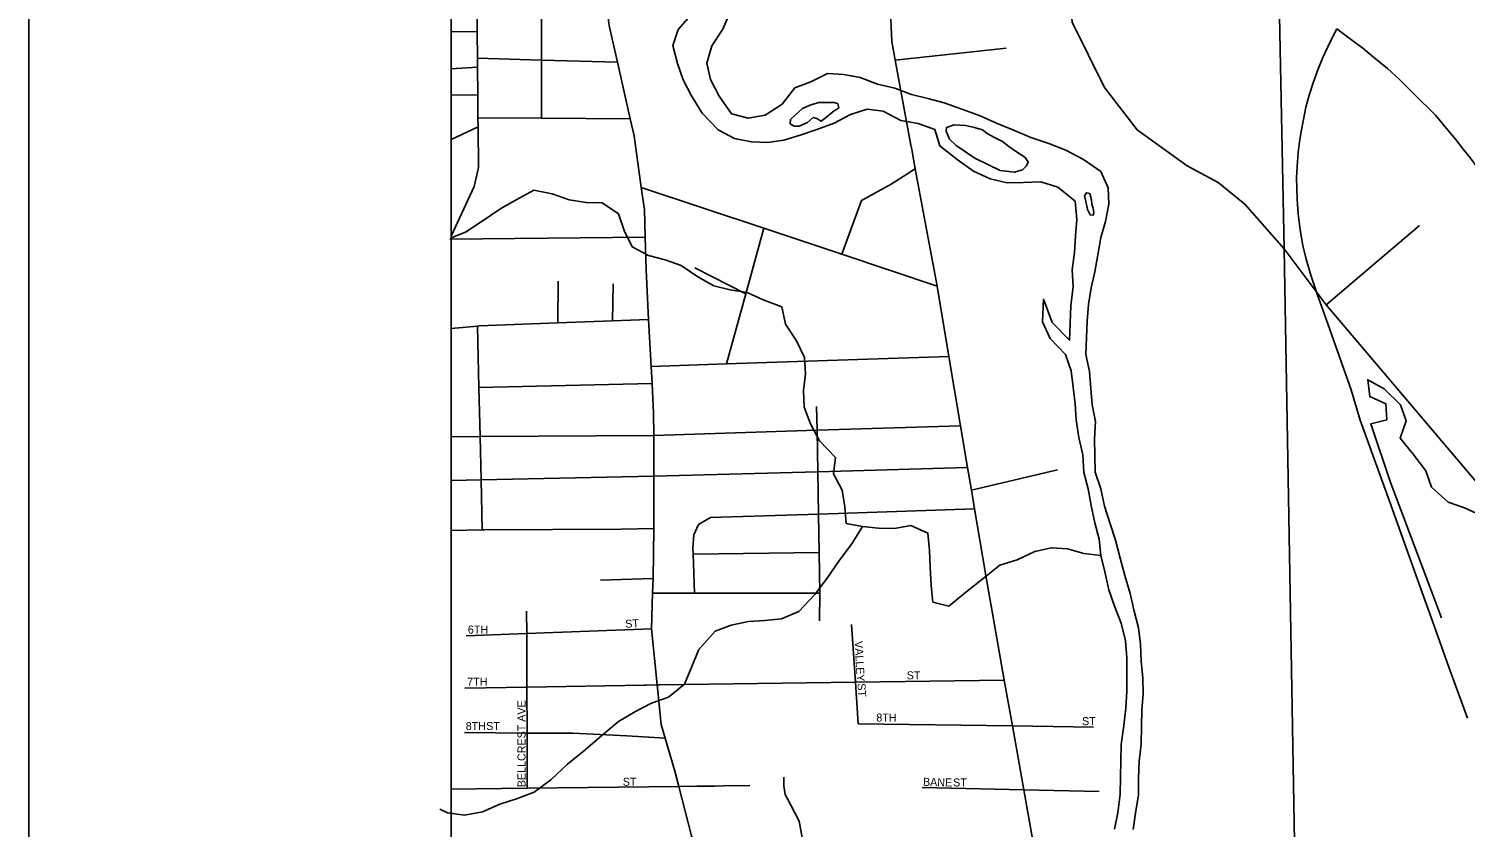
# Model space of a CAD drawing. Extents: x -37878.7 to -37844.7, y -19791.4 to -19769.4.
# Drawn here: x -37876.65 to -37874.951, y -19773.183 to -19772.239 of the extents above; entities that cross this region are included whole.
import ezdxf

# ---------------------------------------------------------------- set-up
doc = ezdxf.new("R2010")
doc.units = 0
for name, color, linetype in [('GM_X_City_Street', 7, 'Continuous'), ('GM_X_County_Road', 7, 'Continuous'), ('GM_X_Major_River', 7, 'Continuous'), ('GM_X_Minor_River', 7, 'Continuous'), ('GM_X_Rail_Line', 7, 'Continuous'), ('GM_X_State_Route', 7, 'Continuous'), ('GM_X_Township', 7, 'Continuous'), ('GM_X_Township_Subdivision', 7, 'Continuous'), ('GM_X_Township_Subdivision_Text', 7, 'Continuous'), ('SH_Border', 7, 'Continuous'), ('SH_Data', 7, 'Continuous')]:
    doc.layers.add(name, color=color, linetype=linetype)

msp = doc.modelspace()

# ---------------------------------------------------------------- linework, layer by layer
at = {"layer": 'GM_X_City_Street'}
for points in [[(-37875.146, -19772.5239), (-37875.1648, -19772.4986), (-37875.2116, -19772.4458), (-37875.243, -19772.4204), (-37875.2799, -19772.4006), (-37875.3389, -19772.3581), (-37875.3775, -19772.308), (-37875.416, -19772.2309), (-37875.4204, -19772.1824), (-37875.4323, -19771.9563)], [(-37875.9135, -19772.9483), (-37875.9122, -19772.9059), (-37875.9117, -19772.8885), (-37875.9108, -19772.8296), (-37875.9109, -19772.7676), (-37875.9109, -19772.7194), (-37875.911, -19772.6933), (-37875.9128, -19772.6581), (-37875.9139, -19772.6379), (-37875.9169, -19772.5822), (-37875.92, -19772.5236), (-37875.9209, -19772.4851), (-37875.9217, -19772.4523), (-37875.9256, -19772.4261), (-37875.9342, -19772.365), (-37875.9387, -19772.345), (-37875.9538, -19772.2781), (-37875.9632, -19772.2368), (-37875.9642, -19772.2318), (-37875.9748, -19772.1441), (-37875.9732, -19772.0332), (-37875.9723, -19771.9774)], [(-37876.0436, -19772.3444), (-37876.0436, -19772.2756), (-37876.0436, -19772.1572), (-37876.0436, -19772.0909), (-37876.0382, -19772.0362)], [(-37875.6056, -19772.3812), (-37875.6065, -19772.3761), (-37875.6251, -19772.2758), (-37875.6293, -19772.2535), (-37875.6314, -19772.201), (-37875.6347, -19772.121), (-37875.6353, -19772.1059)], [(-37876.1504, -19772.2416), (-37876.1197, -19772.2422)], [(-37876.1194, -19772.2734), (-37876.0436, -19772.2756), (-37875.9538, -19772.2781)], [(-37875.6251, -19772.2758), (-37875.494, -19772.2615)], [(-37876.1504, -19772.2861), (-37876.1194, -19772.284)], [(-37876.1504, -19772.3171), (-37876.1191, -19772.3166)], [(-37876.1189, -19772.344), (-37876.0436, -19772.3444), (-37875.9387, -19772.345)], [(-37876.1504, -19772.3694), (-37876.1188, -19772.3546)], [(-37875.5148, -19772.9033), (-37875.518, -19772.8852), (-37875.5312, -19772.8063), (-37875.535, -19772.7841), (-37875.5395, -19772.7575), (-37875.5478, -19772.7081), (-37875.5616, -19772.626), (-37875.5756, -19772.5429), (-37875.6014, -19772.404), (-37875.6056, -19772.3812)], [(-37875.6885, -19772.5052), (-37875.6652, -19772.4415), (-37875.6299, -19772.4223), (-37875.6014, -19772.404)], [(-37875.9256, -19772.4261), (-37875.7806, -19772.4745), (-37875.6885, -19772.5052), (-37875.5756, -19772.5429)], [(-37875.8247, -19772.6349), (-37875.802, -19772.5521), (-37875.7806, -19772.4745)], [(-37875.1154, -19772.5651), (-37875.005, -19772.4711)], [(-37876.152, -19772.4874), (-37875.9209, -19772.4851)], [(-37875.802, -19772.5521), (-37875.8624, -19772.5213)], [(-37874.9569, -19772.7519), (-37875.1154, -19772.5651), (-37875.146, -19772.5239)], [(-37876.0242, -19772.5864), (-37876.0238, -19772.537)], [(-37875.9598, -19772.5839), (-37875.9588, -19772.5402)], [(-37876.1504, -19772.5932), (-37876.1194, -19772.5902), (-37876.1173, -19772.59), (-37876.0242, -19772.5864), (-37875.9598, -19772.5839), (-37875.9169, -19772.5822)], [(-37876.1138, -19772.8313), (-37876.1152, -19772.7719), (-37876.1164, -19772.7208), (-37876.1177, -19772.6628), (-37876.1194, -19772.5902)], [(-37875.9139, -19772.6379), (-37875.8247, -19772.6349), (-37875.5616, -19772.626)], [(-37876.1177, -19772.6628), (-37875.9128, -19772.6581)], [(-37875.7146, -19772.9389), (-37875.7144, -19772.9059), (-37875.7152, -19772.8581), (-37875.716, -19772.8124), (-37875.7168, -19772.7624), (-37875.7177, -19772.7134), (-37875.7182, -19772.6851)], [(-37876.1504, -19772.7211), (-37876.1164, -19772.7208), (-37875.9109, -19772.7194), (-37875.7177, -19772.7134), (-37875.5478, -19772.7081)], [(-37876.1504, -19772.7726), (-37876.1152, -19772.7719), (-37875.9109, -19772.7676), (-37875.7168, -19772.7624), (-37875.5395, -19772.7575)], [(-37875.535, -19772.7841), (-37875.4332, -19772.7602)], [(-37875.8627, -19772.9059), (-37875.8644, -19772.8597), (-37875.8646, -19772.8529), (-37875.8636, -19772.8369), (-37875.8578, -19772.825), (-37875.8436, -19772.8166), (-37875.716, -19772.8124), (-37875.5312, -19772.8063)], [(-37876.1504, -19772.8318), (-37876.1138, -19772.8313), (-37876.1116, -19772.8312), (-37875.9493, -19772.8303), (-37875.9108, -19772.8296)], [(-37875.8644, -19772.8597), (-37875.7152, -19772.8581)], [(-37875.974, -19772.8905), (-37875.9117, -19772.8885)], [(-37875.9122, -19772.9059), (-37875.8627, -19772.9059), (-37875.7144, -19772.9059)]]:
    msp.add_lwpolyline(points, dxfattribs=at)
at = {"layer": 'GM_X_County_Road'}
for points in [[(-37874.8749, -19772.913), (-37874.8745, -19772.8782), (-37874.8783, -19772.8619), (-37874.8861, -19772.8448), (-37874.8985, -19772.8208), (-37874.9569, -19772.7519)], [(-37875.2635, -19774.0864), (-37875.3367, -19773.8513), (-37875.3643, -19773.7721), (-37875.395, -19773.5859), (-37875.4089, -19773.5107), (-37875.4252, -19773.4239), (-37875.4528, -19773.2532), (-37875.4629, -19773.1964), (-37875.4731, -19773.1386), (-37875.4865, -19773.063), (-37875.4961, -19773.0088), (-37875.5105, -19772.9276), (-37875.5148, -19772.9033)], [(-37875.9989, -19774.1065), (-37875.9635, -19773.9001), (-37875.9222, -19773.6825), (-37875.8746, -19773.3908), (-37875.8743, -19773.3891), (-37875.8615, -19773.3214), (-37875.8612, -19773.3198), (-37875.8541, -19773.286), (-37875.8531, -19773.2587), (-37875.8547, -19773.2344), (-37875.8647, -19773.1984), (-37875.8666, -19773.1915), (-37875.8812, -19773.1346), (-37875.8859, -19773.1164), (-37875.8973, -19773.0775), (-37875.902, -19773.0615), (-37875.9068, -19773.0144), (-37875.9135, -19772.9483)]]:
    msp.add_lwpolyline(points, dxfattribs=at)
at = {"layer": 'GM_X_Major_River'}
for p, q in [((-37875.7157, -19772.3258), (-37875.7221, -19772.3278)), ((-37875.5053, -19772.3682), (-37875.5152, -19772.3631)), ((-37875.3995, -19772.443), (-37875.3983, -19772.4483))]:
    msp.add_line(p, q, dxfattribs=at)
for points in [[(-37875.8761, -19772.2989), (-37875.8826, -19772.2796), (-37875.8883, -19772.2585), (-37875.8819, -19772.2394), (-37875.8645, -19772.2197)], [(-37875.7054, -19772.2914), (-37875.7249, -19772.3013), (-37875.7441, -19772.3085), (-37875.7588, -19772.3278), (-37875.779, -19772.3408), (-37875.799, -19772.3443), (-37875.8188, -19772.339), (-37875.8336, -19772.3184), (-37875.8439, -19772.2985), (-37875.8481, -19772.2793), (-37875.8421, -19772.2586), (-37875.8292, -19772.239), (-37875.8209, -19772.2195)], [(-37875.3435, -19773.1854), (-37875.3409, -19773.166), (-37875.3372, -19773.1447), (-37875.3372, -19773.1249), (-37875.3365, -19773.1048), (-37875.3343, -19773.0846), (-37875.3336, -19773.0634), (-37875.3332, -19773.044), (-37875.3317, -19773.025), (-37875.3321, -19773.006), (-37875.334, -19772.9867), (-37875.3349, -19772.9662), (-37875.3375, -19772.9469), (-37875.3429, -19772.9258), (-37875.3471, -19772.9065), (-37875.3536, -19772.885), (-37875.3589, -19772.8646), (-37875.3647, -19772.8435), (-37875.3708, -19772.8239), (-37875.3776, -19772.8031), (-37875.3819, -19772.7827), (-37875.3887, -19772.7631), (-37875.3891, -19772.743), (-37875.3892, -19772.7237), (-37875.3881, -19772.7028), (-37875.3923, -19772.6831), (-37875.3938, -19772.6638), (-37875.3954, -19772.6437), (-37875.3996, -19772.6237), (-37875.3989, -19772.6036), (-37875.3981, -19772.5842), (-37875.3966, -19772.5648), (-37875.3933, -19772.545), (-37875.3891, -19772.5259), (-37875.3854, -19772.5057), (-37875.382, -19772.4855), (-37875.3763, -19772.4664), (-37875.3726, -19772.4458), (-37875.3734, -19772.4265), (-37875.3817, -19772.4073), (-37875.4025, -19772.3933), (-37875.4232, -19772.382), (-37875.4434, -19772.3741), (-37875.4648, -19772.367), (-37875.4862, -19772.358), (-37875.5053, -19772.35), (-37875.5248, -19772.3417), (-37875.5462, -19772.3338), (-37875.5672, -19772.3263), (-37875.5866, -19772.321), (-37875.606, -19772.3162), (-37875.6255, -19772.3086), (-37875.646, -19772.3041), (-37875.6667, -19772.2962), (-37875.6861, -19772.2925), (-37875.7054, -19772.2914)], [(-37875.3659, -19773.1852), (-37875.3618, -19773.1657), (-37875.3592, -19773.1436), (-37875.3588, -19773.1239), (-37875.3581, -19773.1041), (-37875.3578, -19773.0848), (-37875.3548, -19773.0627), (-37875.3522, -19773.0421), (-37875.3511, -19773.022), (-37875.3512, -19772.9825), (-37875.3527, -19772.9624), (-37875.3577, -19772.9416), (-37875.3657, -19772.9213), (-37875.3726, -19772.9021), (-37875.3772, -19772.8806), (-37875.3817, -19772.8613), (-37875.384, -19772.842), (-37875.389, -19772.8228), (-37875.3932, -19772.8023), (-37875.397, -19772.7827), (-37875.402, -19772.7634), (-37875.4032, -19772.7426), (-37875.4078, -19772.7218), (-37875.4112, -19772.701), (-37875.4124, -19772.682), (-37875.4147, -19772.6624), (-37875.417, -19772.643), (-37875.4238, -19772.6238), (-37875.442, -19772.6049), (-37875.4511, -19772.5853), (-37875.4498, -19772.5584), (-37875.4394, -19772.5858), (-37875.4191, -19772.607), (-37875.4174, -19772.5664), (-37875.4145, -19772.5435), (-37875.416, -19772.5238), (-37875.4131, -19772.5033), (-37875.412, -19772.4835), (-37875.4101, -19772.4641), (-37875.4124, -19772.4425), (-37875.4329, -19772.4259), (-37875.4527, -19772.4195), (-37875.4735, -19772.4203), (-37875.4928, -19772.4207), (-37875.513, -19772.4162), (-37875.5325, -19772.4068), (-37875.5517, -19772.3932), (-37875.5722, -19772.3769), (-37875.5782, -19772.3577), (-37875.5981, -19772.3505), (-37875.6186, -19772.3472), (-37875.6393, -19772.3359), (-37875.6583, -19772.3336), (-37875.6782, -19772.3401), (-37875.6974, -19772.35), (-37875.7169, -19772.3573), (-37875.7376, -19772.3642), (-37875.7568, -19772.3703), (-37875.7761, -19772.373), (-37875.7954, -19772.3723), (-37875.8152, -19772.3685), (-37875.8347, -19772.3579), (-37875.8537, -19772.3382), (-37875.8662, -19772.318), (-37875.8761, -19772.2989)], [(-37875.7221, -19772.3278), (-37875.727, -19772.3294), (-37875.7348, -19772.333), (-37875.743, -19772.3404), (-37875.749, -19772.3458), (-37875.7496, -19772.3508), (-37875.7446, -19772.3537), (-37875.739, -19772.3536), (-37875.7288, -19772.3492), (-37875.7221, -19772.3434), (-37875.7179, -19772.3448), (-37875.7129, -19772.3477), (-37875.7081, -19772.3442), (-37875.6988, -19772.3368), (-37875.692, -19772.3321), (-37875.6929, -19772.3275), (-37875.6971, -19772.3257), (-37875.7062, -19772.3259), (-37875.7157, -19772.3258)], [(-37875.5152, -19772.3631), (-37875.5218, -19772.358), (-37875.5313, -19772.3555), (-37875.542, -19772.3531), (-37875.5556, -19772.3523), (-37875.5643, -19772.3555), (-37875.5649, -19772.3597), (-37875.561, -19772.3691), (-37875.5532, -19772.3765), (-37875.5421, -19772.3842), (-37875.5309, -19772.3916), (-37875.5149, -19772.3996), (-37875.5011, -19772.4061), (-37875.484, -19772.408), (-37875.4746, -19772.4052), (-37875.4698, -19772.4005), (-37875.468, -19772.3959), (-37875.4719, -19772.3903), (-37875.4803, -19772.3848), (-37875.4907, -19772.3778), (-37875.4984, -19772.3719), (-37875.5053, -19772.3682)], [(-37875.3983, -19772.4483), (-37875.3978, -19772.4524), (-37875.3947, -19772.4584), (-37875.3909, -19772.4591), (-37875.3902, -19772.4561), (-37875.3911, -19772.4508), (-37875.3927, -19772.4463), (-37875.3928, -19772.4409), (-37875.3948, -19772.4334), (-37875.399, -19772.4324), (-37875.4012, -19772.4362), (-37875.3995, -19772.443)]]:
    msp.add_lwpolyline(points, dxfattribs=at)
at = {"layer": 'GM_X_Minor_River'}
for points in [[(-37875.3817, -19772.8613), (-37875.4022, -19772.8591), (-37875.4213, -19772.8534), (-37875.4403, -19772.8523), (-37875.4599, -19772.8566), (-37875.4809, -19772.8665), (-37875.5012, -19772.873), (-37875.5213, -19772.8887), (-37875.5422, -19772.9054), (-37875.5616, -19772.9214), (-37875.5806, -19772.9165), (-37875.5825, -19772.8968), (-37875.5838, -19772.8752), (-37875.5845, -19772.8555), (-37875.5865, -19772.835), (-37875.6068, -19772.826), (-37875.626, -19772.8294), (-37875.6449, -19772.8291), (-37875.6639, -19772.8272), (-37875.6833, -19772.8235), (-37875.6849, -19772.8038), (-37875.6879, -19772.7841), (-37875.6982, -19772.765), (-37875.6959, -19772.7455), (-37875.7149, -19772.7258), (-37875.7256, -19772.7056), (-37875.7328, -19772.686), (-37875.7336, -19772.6663), (-37875.7313, -19772.6465), (-37875.7325, -19772.6275), (-37875.742, -19772.6076), (-37875.7549, -19772.5878), (-37875.7595, -19772.5674), (-37875.7813, -19772.5591), (-37875.8004, -19772.5504), (-37875.8205, -19772.5474), (-37875.8396, -19772.5425), (-37875.8587, -19772.5319), (-37875.8783, -19772.5187), (-37875.8974, -19772.5119), (-37875.9169, -19772.5066), (-37875.9364, -19772.4964), (-37875.9459, -19772.4773), (-37875.9524, -19772.4573), (-37875.9719, -19772.4444), (-37875.9909, -19772.4441), (-37876.011, -19772.4407), (-37876.0309, -19772.4339), (-37876.0526, -19772.4295), (-37876.0728, -19772.4405), (-37876.0919, -19772.4512), (-37876.1128, -19772.4653), (-37876.1334, -19772.479), (-37876.1504, -19772.4857)], [(-37874.979, -19772.9353), (-37875.0396, -19772.7738), (-37875.0626, -19772.7059), (-37875.0434, -19772.7009), (-37875.0445, -19772.682), (-37875.0637, -19772.6733), (-37875.066, -19772.6536), (-37875.0468, -19772.6642), (-37875.0275, -19772.6831), (-37875.0206, -19772.7023), (-37875.0278, -19772.7226), (-37875.0122, -19772.7416), (-37874.9974, -19772.7614), (-37874.9906, -19772.7807), (-37874.9709, -19772.7984), (-37874.9518, -19772.8052), (-37874.9327, -19772.8136), (-37874.9132, -19772.82), (-37874.9011, -19772.8398), (-37874.8999, -19772.8432)], [(-37875.6639, -19772.8272), (-37875.6764, -19772.8476), (-37875.6911, -19772.8669), (-37875.7058, -19772.8881), (-37875.7202, -19772.9074), (-37875.7391, -19772.9276), (-37875.7598, -19772.9364), (-37875.7794, -19772.9383), (-37875.7987, -19772.9395), (-37875.8191, -19772.9437), (-37875.8383, -19772.951), (-37875.8575, -19772.9726), (-37875.8658, -19772.9926), (-37875.8745, -19773.0136), (-37875.8935, -19773.0292), (-37875.9134, -19773.0361), (-37875.9333, -19773.0464), (-37875.9527, -19773.0578), (-37875.9721, -19773.0742), (-37875.9922, -19773.0913), (-37876.013, -19773.1081), (-37876.0327, -19773.1267), (-37876.0525, -19773.1412), (-37876.0732, -19773.1493), (-37876.0928, -19773.1554), (-37876.1134, -19773.1645), (-37876.1349, -19773.1684), (-37876.1547, -19773.1658), (-37876.1639, -19773.1615)]]:
    msp.add_lwpolyline(points, dxfattribs=at)
at = {"layer": 'GM_X_Rail_Line'}
for points in [[(-37874.948, -19773.054), (-37874.9702, -19772.9937), (-37874.9874, -19772.9448), (-37875.0088, -19772.8857), (-37875.0389, -19772.8014), (-37875.0749, -19772.7016), (-37875.0857, -19772.6657), (-37875.1084, -19772.6007), (-37875.1175, -19772.5752), (-37875.1257, -19772.5535), (-37875.1335, -19772.5299), (-37875.1389, -19772.5111), (-37875.1427, -19772.4947), (-37875.1461, -19772.4763), (-37875.1484, -19772.4576), (-37875.1497, -19772.4403), (-37875.15, -19772.4267), (-37875.1502, -19772.4145), (-37875.1492, -19772.3961), (-37875.1483, -19772.3849), (-37875.1468, -19772.3721), (-37875.145, -19772.3602), (-37875.1423, -19772.3457), (-37875.1393, -19772.3314), (-37875.1353, -19772.317), (-37875.1303, -19772.3014), (-37875.1251, -19772.287), (-37875.1194, -19772.2724), (-37875.1107, -19772.2538), (-37875.1028, -19772.2385)], [(-37874.6273, -19772.9339), (-37874.6529, -19772.8899), (-37874.6818, -19772.8388), (-37874.7281, -19772.7578), (-37874.7648, -19772.6936), (-37874.8424, -19772.5579), (-37874.8781, -19772.4953), (-37874.9128, -19772.4366), (-37874.925, -19772.4185), (-37874.9369, -19772.4018), (-37874.9446, -19772.3914), (-37874.9531, -19772.3808), (-37874.9621, -19772.3691), (-37874.9709, -19772.3587), (-37874.9861, -19772.3408), (-37875.0118, -19772.315), (-37875.029, -19772.2981), (-37875.0428, -19772.2854), (-37875.0592, -19772.272), (-37875.0718, -19772.2616), (-37875.082, -19772.2538), (-37875.1028, -19772.2385)]]:
    msp.add_lwpolyline(points, dxfattribs=at)
at = {"layer": 'GM_X_State_Route'}
for points in [[(-37876.1188, -19772.3546), (-37876.1189, -19772.344), (-37876.1191, -19772.3166), (-37876.1194, -19772.284), (-37876.1194, -19772.2734), (-37876.1197, -19772.2422), (-37876.12, -19772.2007), (-37876.1088, -19772.1449), (-37876.1084, -19772.1147), (-37876.1096, -19772.0824), (-37876.11, -19772.0668), (-37876.1084, -19772.0387), (-37876.1075, -19771.977)], [(-37876.1504, -19772.484), (-37876.1232, -19772.4251), (-37876.1184, -19772.4026), (-37876.1188, -19772.3546)]]:
    msp.add_lwpolyline(points, dxfattribs=at)
at = {"layer": 'GM_X_Township'}
for points in [[(-37875.2046, -19770.3854), (-37875.2045, -19770.3883), (-37875.1996, -19770.7262), (-37875.1932, -19770.9906), (-37875.1922, -19771.0645), (-37875.1913, -19771.1313), (-37875.1903, -19771.2032), (-37875.1894, -19771.2701), (-37875.1885, -19771.3343), (-37875.1874, -19771.4123), (-37875.1857, -19771.5367), (-37875.1848, -19771.6035), (-37875.1845, -19771.6245), (-37875.184, -19771.6631), (-37875.1834, -19771.7048), (-37875.1821, -19771.8044), (-37875.1759, -19771.948), (-37875.1648, -19772.4986), (-37875.1373, -19774.0823), (-37875.2635, -19774.0864), (-37875.9989, -19774.1065), (-37876.1504, -19774.1098)], [(-37875.1373, -19774.0823), (-37875.1648, -19772.4986), (-37875.1759, -19771.948), (-37875.1821, -19771.8044), (-37875.1834, -19771.7048), (-37875.184, -19771.6631), (-37875.1845, -19771.6245), (-37875.1848, -19771.6035), (-37875.1857, -19771.5367), (-37875.1874, -19771.4123), (-37875.1885, -19771.3343), (-37875.1894, -19771.2701), (-37875.1903, -19771.2032), (-37875.1913, -19771.1313), (-37875.1922, -19771.0645), (-37875.1932, -19770.9906), (-37875.1996, -19770.7262), (-37875.2045, -19770.3883), (-37875.2046, -19770.3854)]]:
    msp.add_lwpolyline(points, dxfattribs=at)
at = {"layer": 'GM_X_Township_Subdivision'}
for points in [[(-37876.0605, -19773.1367), (-37876.0608, -19773.0714), (-37876.061, -19773.017), (-37876.0612, -19772.9537), (-37876.0613, -19772.9272)], [(-37876.133, -19772.9563), (-37876.0612, -19772.9537), (-37875.9135, -19772.9483)], [(-37875.6689, -19773.0607), (-37875.6722, -19773.0112), (-37875.6769, -19772.9429)], [(-37876.1343, -19773.0182), (-37876.061, -19773.017), (-37875.9219, -19773.0147), (-37875.9197, -19773.0147)], [(-37875.9197, -19773.0147), (-37875.9068, -19773.0144), (-37875.9037, -19773.0144), (-37875.6722, -19773.0112), (-37875.4961, -19773.0088)], [(-37876.1348, -19773.0709), (-37876.0608, -19773.0714), (-37876.0065, -19773.0717), (-37875.9426, -19773.0749), (-37875.8973, -19773.0775)], [(-37875.6689, -19773.0607), (-37875.4865, -19773.063), (-37875.3905, -19773.0643)], [(-37875.7331, -19773.257), (-37875.7301, -19773.2378), (-37875.729, -19773.223), (-37875.7348, -19773.1972), (-37875.7387, -19773.1755), (-37875.749, -19773.1558), (-37875.7555, -19773.1441), (-37875.7571, -19773.1339), (-37875.7571, -19773.1236)], [(-37876.1504, -19773.1377), (-37876.0605, -19773.1367), (-37875.8812, -19773.1346)], [(-37875.8812, -19773.1346), (-37875.8597, -19773.1343), (-37875.8391, -19773.1341)], [(-37875.8391, -19773.1341), (-37875.8283, -19773.134), (-37875.797, -19773.1336)], [(-37875.5934, -19773.136), (-37875.4731, -19773.1386), (-37875.3837, -19773.1406)]]:
    msp.add_lwpolyline(points, dxfattribs=at)
at = {"layer": 'SH_Border'}
msp.add_lwpolyline([(-37876.6504, -19769.8854), (-37845.1504, -19769.8854), (-37845.1504, -19790.8854), (-37876.6504, -19790.8854)], close=True, dxfattribs=at)
at = {"layer": 'SH_Data'}
msp.add_line((-37876.1504, -19770.3854), (-37876.1504, -19777.3854), dxfattribs=at)

# ---------------------------------------------------------------- texts
at = {"layer": 'GM_X_Township_Subdivision_Text'}
for s, rotation, p in [('ST', 3.5814, (-37875.9443, -19772.9471)), ('6TH', 0, (-37876.1308, -19772.9538)), ('VALLEY', 273.0687, (-37875.6732, -19772.9629)), ('7TH', 0, (-37876.1316, -19773.0154)), ('ST', 0, (-37875.6116, -19773.0079)), ('ST', 273.5746, (-37875.6699, -19773.0129)), ('BELLCREST AVE', 90, (-37876.0626, -19773.1355)), ('8TH', 0, (-37876.1333, -19773.0679)), ('ST', 0, (-37876.1091, -19773.0679)), ('8TH', 0, (-37875.6475, -19773.0579)), ('ST', 0, (-37875.4041, -19773.0621)), ('ST', 0, (-37875.9475, -19773.1338)), ('BANE', 358.4935, (-37875.5924, -19773.1338)), ('ST', 0, (-37875.5566, -19773.1346))]:
    msp.add_text(s, height=0.00947, rotation=rotation, dxfattribs=at).set_placement(p)

doc.saveas('drawing.dxf')
